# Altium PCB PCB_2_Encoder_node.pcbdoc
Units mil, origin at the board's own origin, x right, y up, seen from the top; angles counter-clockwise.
Board outline 2066.54 x 1941.84 mil, 2 copper layers (Top Layer, Bottom Layer), stack 2.757 mil thick; 20 components, 22 nets, 103 pads, 62 vias.
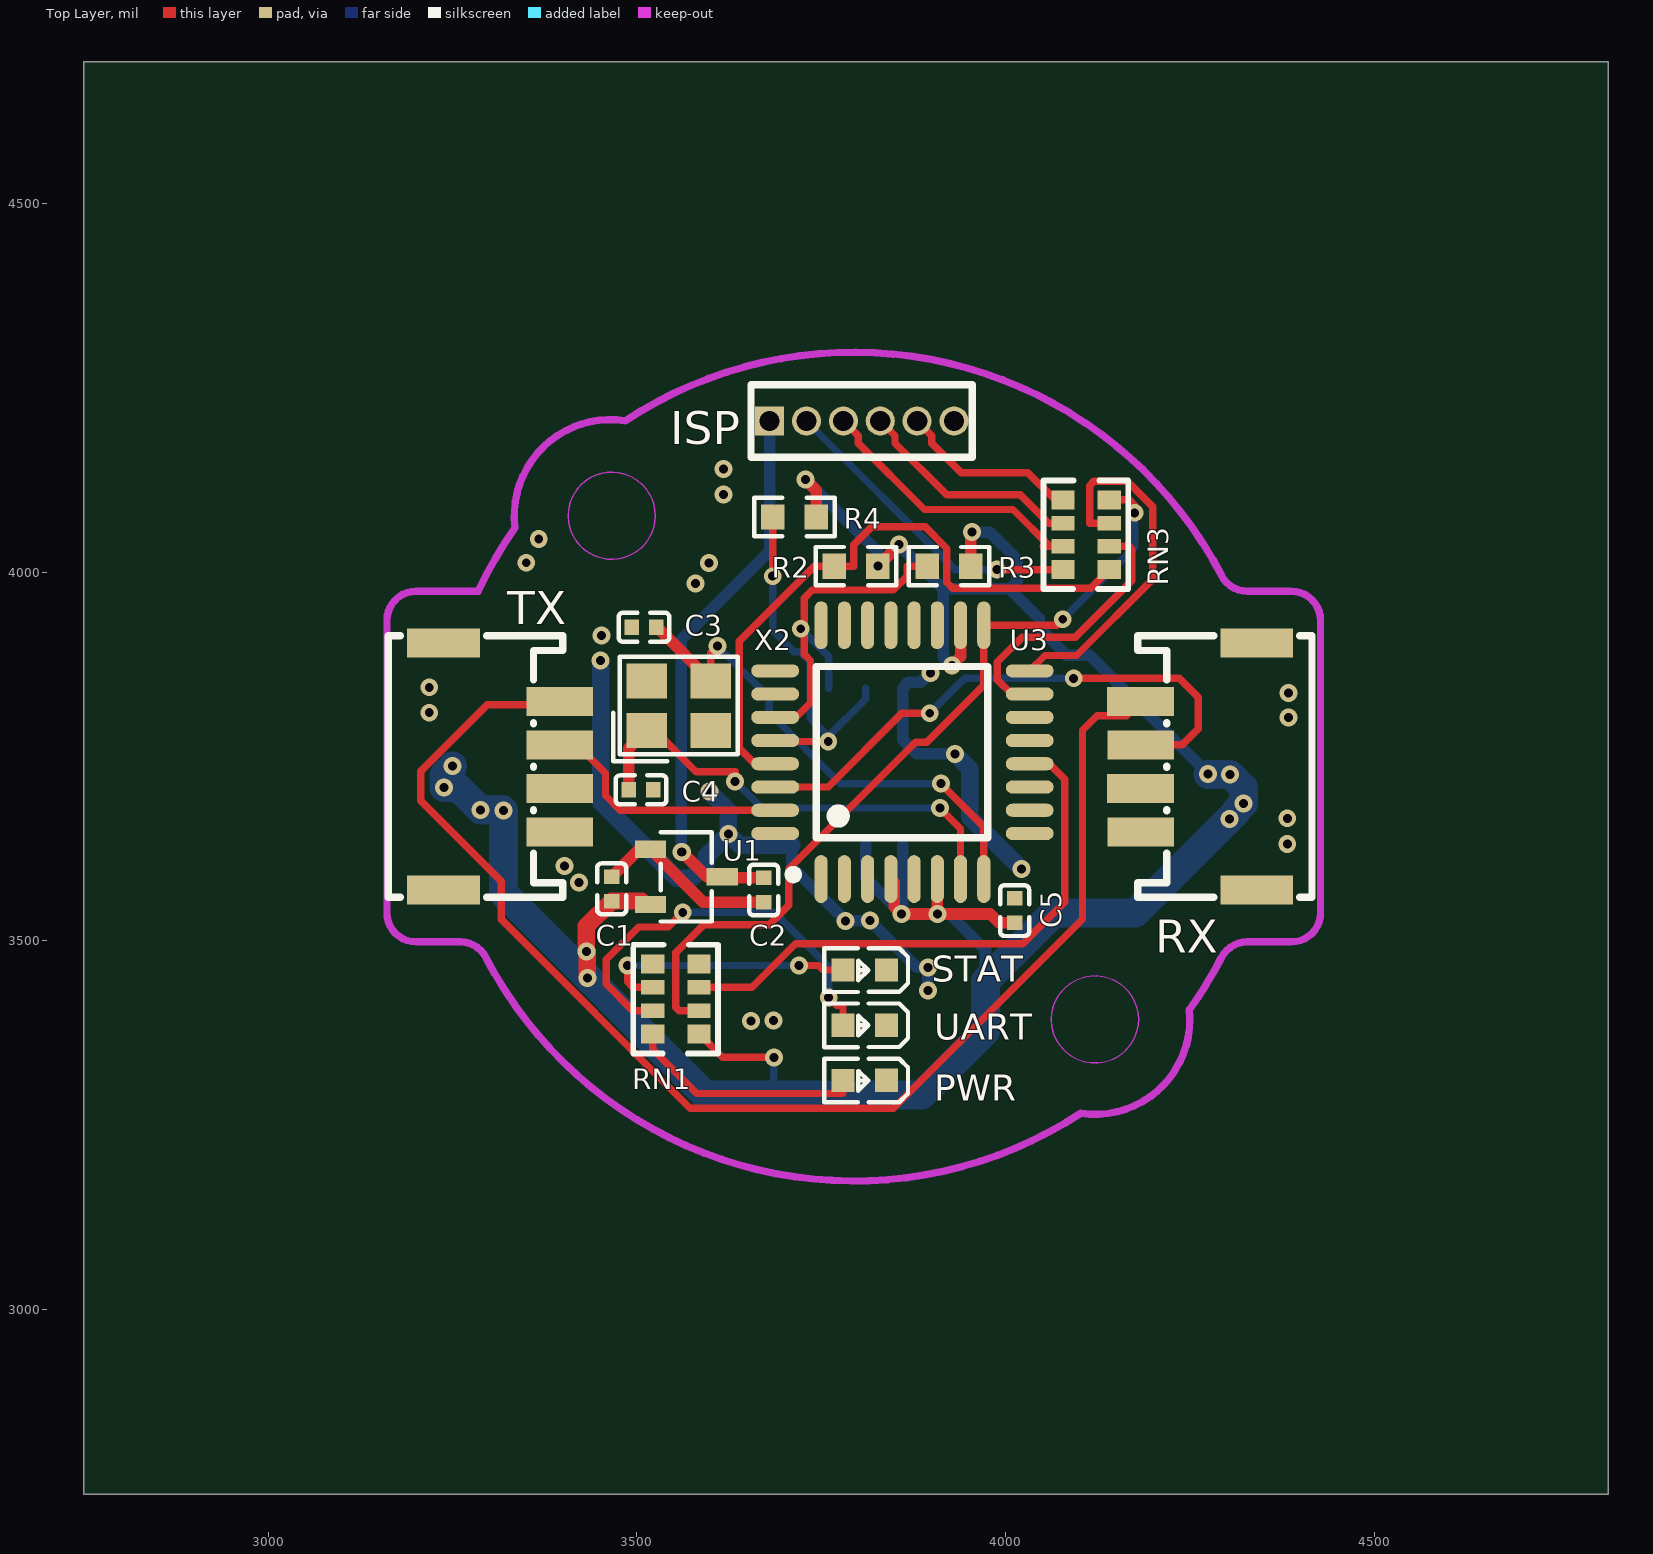
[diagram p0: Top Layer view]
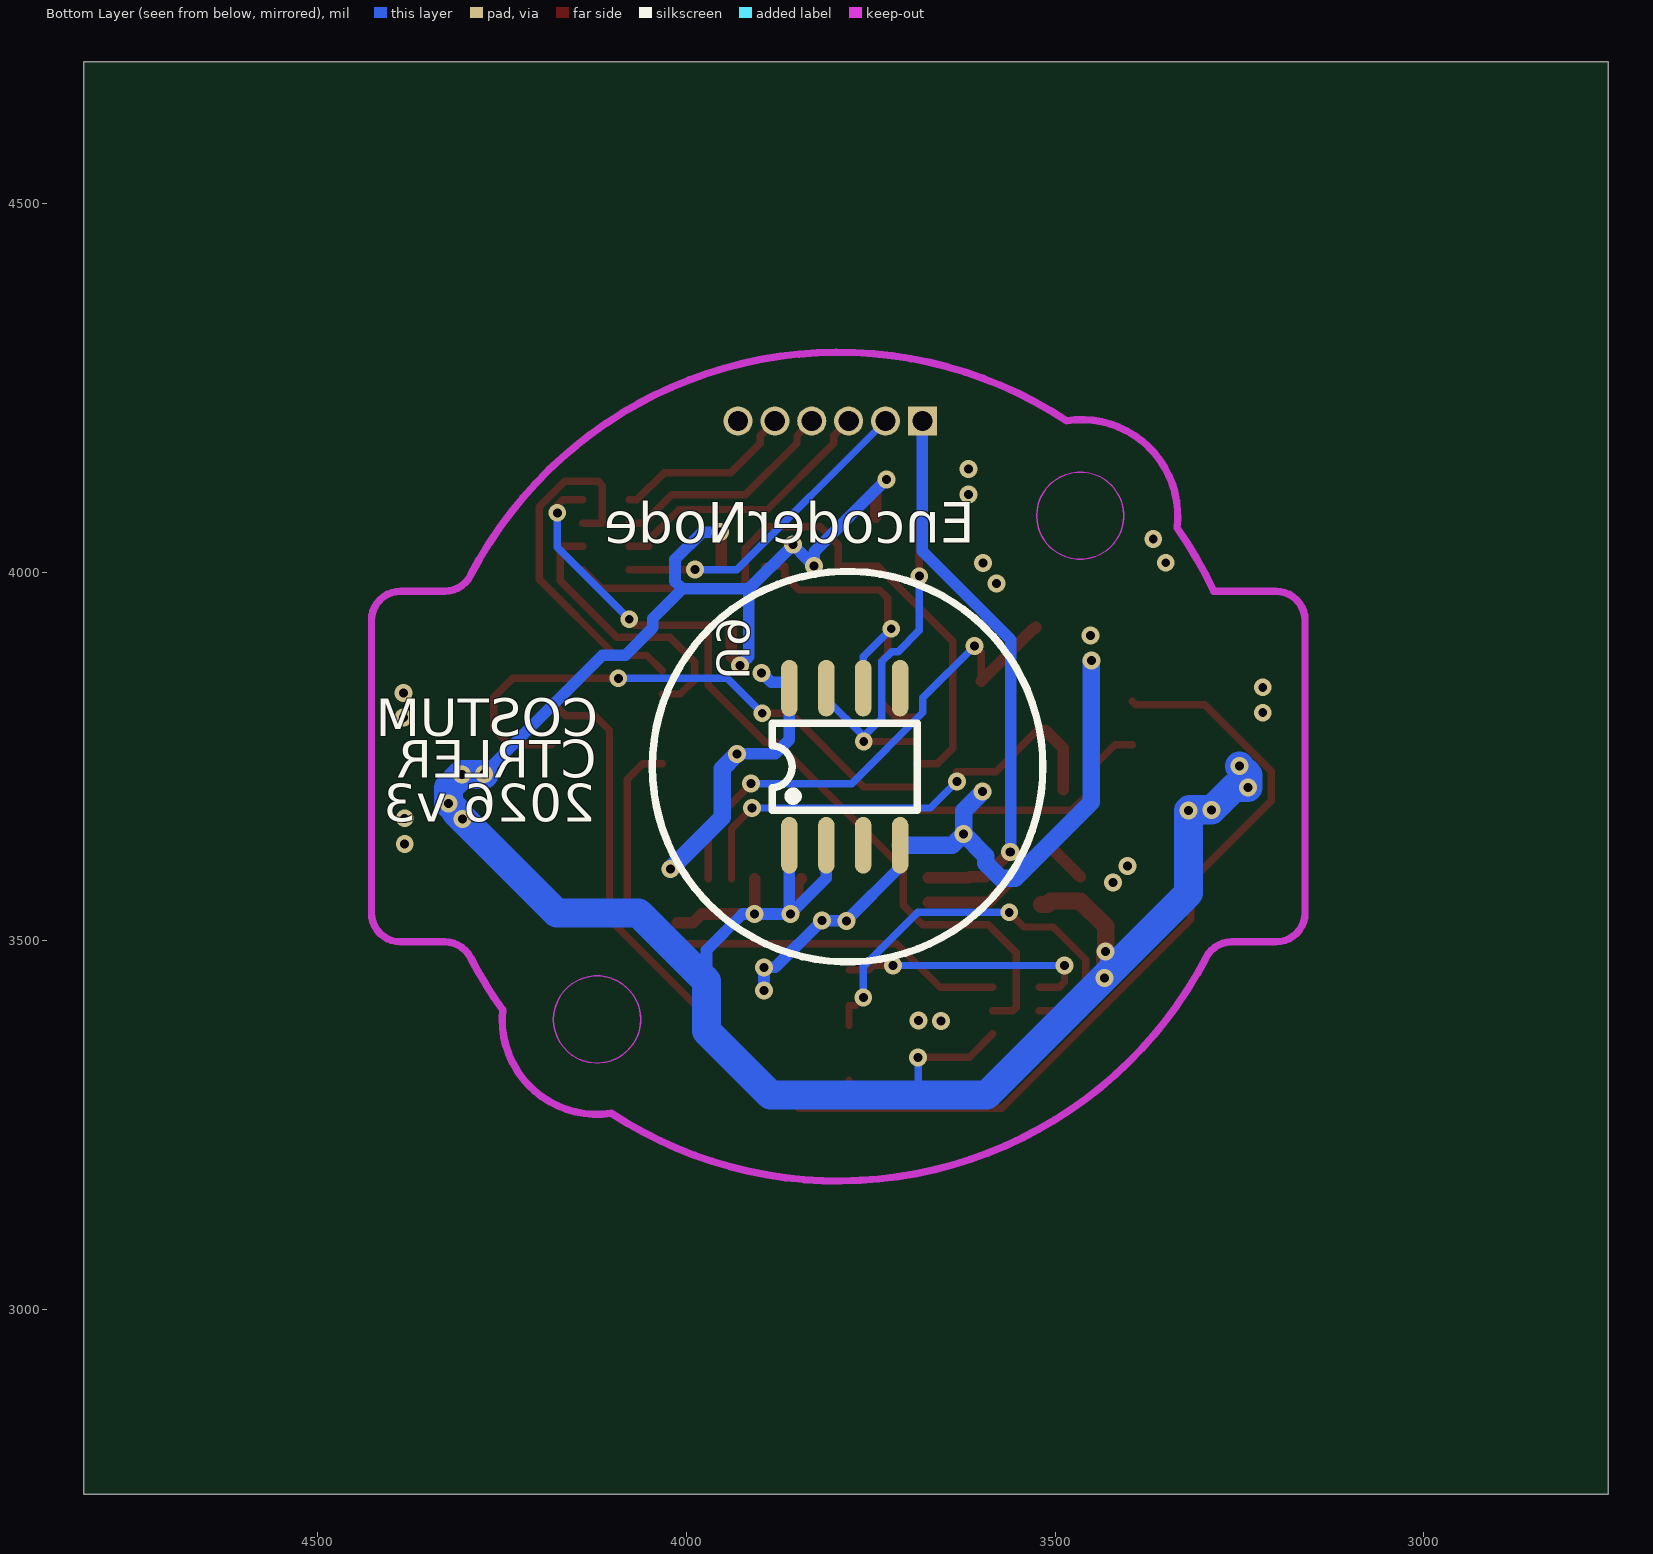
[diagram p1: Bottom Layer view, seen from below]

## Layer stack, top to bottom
Top Solder Mask Layer: solder mask 0.394, Dk 3.3
Top Layer: signal copper 1.379
Bottom Layer: signal copper 1.378
Bottom Solder Mask Layer: solder mask 0.394, Dk 3.3

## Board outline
4816.54,2750 2750,2750 2750,4691.84 4816.54,4691.84

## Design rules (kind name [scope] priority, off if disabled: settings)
BoardOutlineClearance Default [All] p0: genericclearance=10 ignorepadtopadclearanceinfootprint=FALSE except(0: Arc-SplitContinuation Track-SplitContinuation SMDPad-SplitContinuation THPad-SplitContinuation Via-SplitContinuation Fill-SplitContinuation Poly-SplitContinuation Region-SplitContinuation Text-SplitContinuation)
BoardOutlineClearance otherClearance [All] p0: genericclearance=10 ignorepadtopadclearanceinfootprint=FALSE except(0: Arc-SplitContinuation Track-SplitContinuation SMDPad-SplitContinuation THPad-SplitContinuation Via-SplitContinuation Fill-SplitContinuation Poly-SplitContinuation Region-SplitContinuation Text-SplitContinuation)
Clearance Default [All] p1: gap=7 ignorepadtopadclearanceinfootprint=FALSE
Clearance otherClearance [All] p1: gap=7 ignorepadtopadclearanceinfootprint=FALSE
DiffPairsRouting differentialPair [All] p1: maxuncoupledlength=10 minlimit=5 maxlimit=Infinity mostfreqgap=6 toplayer_minwidth=5 toplayer_prefwidth=100 toplayer_maxwidth=100 bottomlayer_minwidth=5 bottomlayer_prefwidth=100 bottomlayer_maxwidth=100
PasteMaskExpansion pasteMaskExpansion [All] p1: expansion=0
PlaneConnect innerPlane [All] p1: planeconnectstyle=Relief reliefexpansion=20 reliefentries=4 reliefconductorwidth=10 reliefairgap=10
PolygonConnect copperRegion [All] p1: connectstyle=Relief reliefentries=4 reliefconductorwidth=10 polygonreliefangle="90 Angle" airgapwidth=10
RoutingVias Default [All] p1: viastyle="Through Hole" holewidth=12.008000000000001 minholewidth=12.008000000000001 maxholewidth=1181 width=12.008000000000001 minwidth=12.008000000000001 maxwidth=1181
SolderMaskExpansion Common [IsVia] p1: useseparateexpansions=TRUE expansion=-1000 expansionbottom=-1000
SolderMaskExpansion Common [All] p2: useseparateexpansions=TRUE expansion=2 expansionbottom=2
Width Default [All] p1: maxlimit=1000 minlimit=10 preferedwidth=10

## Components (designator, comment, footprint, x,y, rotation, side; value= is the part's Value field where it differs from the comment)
C1 "1uF" C0402 3465.71,3570.71 r270 top
C2 "1uF" C0402 3671.77,3569.13 r90 top
C3 "15pf" C0402 3509.41,3925.27 r0 top
C4 "15pf" C0402 3505.47,3704.8 r0 top
C5 "100pf" C0402 4011.79,3541.16 r90 top
ISP "6PIN" HDR-TH_6P-P1.27-V-M 3804.68,4204.8 r0 top
PWR "GL0603UG01" LED0603-RD 3808.62,3311.1 r180 top
R2 "10kΩ" R0603 3796.81,4007.95 r0 top
R3 "10kΩ" R0603 3922.79,4007.95 r0 top
R4 "10kΩ" R0603 3713.53,4074.64 r0 top
RN1 "4.7kΩ" RES-ARRAY-SMD_0603-8P-L3.2-W1.6-BL 3552.72,3421.33 r90 top
RN3 "1kΩ" RES-ARRAY-SMD_0603-8P-L3.2-W1.6-BL 4108.72,4050.6 r90 top
RX "RX" CONN-SMD_4P-P1.50_ZX-ZH1.5-4PWT 4261.38,3736.29 r90 top
STAT "GL0603UG01" LED0603-RD 3808.59,3460.73 r180 top
TX "TX" CONN-SMD_4P-P1.50_ZX-ZH1.5-4PWT 3316.49,3736.29 r270 top
U1 "XC6206P332MR" SOT-23-3_L2.9-W1.6-P1.90-LS2.8-BR 3566.97,3586.86 r180 top
U3 "ATMEGA328P-AU" TQFP-32_L7.0-W7.0-P0.80-LS9.0-BL 3859.77,3755.96 r0 top
U9 "AS5600-ASOT" SOIC-8_L5.0-W4.0-P1.27-LS6.0-BL 3784.97,3736.26 r180 bottom
UART "GL0603UG01" LED0603-RD 3808.59,3385.93 r180 top
X2 "8MHz" CRYSTAL-SMD_4P-L3.2-W2.5-BL 3556.65,3818.97 r0 top

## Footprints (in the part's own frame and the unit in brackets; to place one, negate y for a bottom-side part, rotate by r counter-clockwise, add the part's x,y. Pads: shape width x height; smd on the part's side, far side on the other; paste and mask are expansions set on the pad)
C0402 [mm]
  rect 0.5x0.54 smd paste+0 mask+0.051: 1(-0.42,0) 2(0.42,0)
  silkscreen extent -0.87,-0.5 0.87,0.5
CONN-SMD_4P-P1.50_ZX-ZH1.5-4PWT [mm]
  rect 1x2.3 smd paste+0 mask+0.05: 1(-2.25,2) 2(-0.75,2) 3(0.75,2) 4(2.25,2)
  rect 1x2.5 smd paste+0 mask+0.05: 5(4.25,-2) 6(-4.25,-2)
  silkscreen extent -4.5,-3.9 4.5,2.1
CRYSTAL-SMD_4P-L3.2-W2.5-BL [mm]
  rect 1.4x1.2 smd paste+0 mask+0.051: 1(-1.1,-0.85) 2(1.1,-0.85) 3(1.1,0.85) 4(-1.1,0.85)
  silkscreen extent -2.26,-1.91 2.03,1.68
HDR-TH_6P-P1.27-V-M [mm]
  rect 1x1 hole 0.7 paste+0 mask+0.051: 1(-3.175,0)
  round 1 hole 0.7 paste+0 mask+0.051: 2(-1.905,0) 3(-0.635,0) 4(0.635,0) 5(1.905,0) 6(3.175,0)
  silkscreen extent -3.82,-1.25 3.8,1.25
LED0603-RD [mm]
  rect 0.8x0.8 smd paste+0 mask+0.051: 1(-0.749,0) 2(0.749,0)
  silkscreen extent -1.49,-0.75 1.39,0.76
R0603 [mil]
  rect 31.75x34.02 smd paste-3937.01 mask+2: 1(-29.66,0) 2(29.65,0)
  silkscreen extent -55,-26 55,26
RES-ARRAY-SMD_0603-8P-L3.2-W1.6-BL [mm]
  rect 0.65x0.8 smd paste+0 mask+0.051: 1(-1.2,-0.8) 4(1.2,-0.8) 5(1.2,0.8) 8(-1.2,0.8)
  rect 0.5x0.8 smd paste+0 mask+0.051: 2(-0.4,-0.8) 3(0.4,-0.8) 6(0.4,0.8) 7(-0.4,0.8)
  silkscreen extent -1.87,-1.45 1.87,1.47
SOIC-8_L5.0-W4.0-P1.27-LS6.0-BL [mil]
  oval 22.38x76.78 smd paste+0 mask+2: 1(-75,-106.5) 2(-25,-106.5) 3(25,-106.5) 4(75,-106.5) 5(75,106.5) 6(25,106.5) 7(-25,106.5) 8(-75,106.5)
  silkscreen extent -98,-59 98,59
SOT-23-3_L2.9-W1.6-P1.90-LS2.8-BR [mm]
  rect 1.07x0.6 smd paste+0 mask+0.051: 1(1.235,-0.95) 2(1.235,0.95) 3(-1.235,0)
  silkscreen extent -0.88,-1.54 0.88,1.54
TQFP-32_L7.0-W7.0-P0.80-LS9.0-BL [mm]
  oval 0.45x1.65 smd paste+0 mask+0.051: 1(-2.8,-4.369) 2(-2,-4.369) 3(-1.2,-4.369) 4(-0.4,-4.369) 5(0.4,-4.369) 6(1.2,-4.369) 7(2,-4.369) 8(2.8,-4.369) 17(2.8,4.369) 18(2,4.369) 19(1.2,4.369) 20(0.4,4.369) 21(-0.4,4.369) 22(-1.2,4.369) 23(-2,4.369) 24(-2.8,4.369)
  oval 1.65x0.45 smd paste+0 mask+0.051: 9(4.381,-2.8) 10(4.381,-2) 11(4.381,-1.2) 12(4.381,-0.4) 13(4.381,0.4) 14(4.381,1.2) 15(4.381,2) 16(4.381,2.8) 25(-4.381,2.8) 26(-4.381,2) 27(-4.381,1.2) 28(-4.381,0.4) 29(-4.381,-0.4) 30(-4.381,-1.2) 31(-4.381,-2) 32(-4.381,-2.8)
  silkscreen extent -3.91,-4.36 2.94,2.95

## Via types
v1: diameter 24.41, hole 12.2, Top Layer to Bottom Layer, 44 vias
v2: diameter 24.02, hole 12.01, Top Layer to Bottom Layer, 18 vias

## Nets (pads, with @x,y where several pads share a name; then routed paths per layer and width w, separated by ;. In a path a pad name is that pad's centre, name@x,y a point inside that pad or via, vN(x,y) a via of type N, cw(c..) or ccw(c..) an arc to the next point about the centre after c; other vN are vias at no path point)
3V3: C1.2 C5.1 R2.2 R3.2 R4.2 RN1.1 RX.2 TX.3 U1.2 U3.4 U3.6 U3.18 U9.1 U9.2 | length 3855.3
  Top Layer w10: RN1.1 3616.12,3342.19 v1(3685.56,3342.19)
  Top Layer w15.75: v1(3728.51,4125.46) 3743.19,4110.78 R4.2 ; R2.2@3826.47,4007.96 3834.97,4016.46 v1(3854.98,4037.21) ; U3.4 3848.78,3579.25 3848.78,3546.53 v1(3858.78,3536.53) 3978.78,3536.53 3990.69,3524.62 C5.1 ; v1(3907.04,3536.53) U3.6 ; v1(3926.69,3873.7) 3938.54,3885.55 U3.18 ; R3.2 3952.45,4052.33 v1(3954.27,4054.15)
  Top Layer w23.62: v1(3432.61,3449.75) 3432.61,3485.61 v1(3431.43,3485.61) 3431.43,3519.89 C1.2 3505.71,3554.17 3510.41,3549.46 U1.2
  Bottom Layer w10: v1(3685.56,3342.19) 3685.56,3302.19 3687.62,3300.13 3687.62,3291.36
  Bottom Layer w15.75: v1(3431.43,3485.61) 3431.43,3449.75 v1(3432.61,3449.75) 3437.68,3449.75 3440.46,3446.97 v1@3440.46,3443.48 ; v1(3728.51,4125.46) 3826.46,4027.51 v1(3826.46,4007.95) 3834.97,4016.46 v1(3854.98,4037.21) ; U9.2 3810,3585.31 v1(3858.78,3536.53) ; v1(3854.98,4037.21) 3914.98,3977.2 ; U9.1 3860,3537.75 v1(3858.78,3536.53) ; v1(3926.69,3873.7) 3914.98,3885.4 3914.98,3977.2 ; v1(3954.27,4054.15) 3978.04,4054.15 4014.98,4017.2 4014.98,3987.2 4004.98,3977.2 3914.98,3977.2 ; 3972.37,3445.86 3972.37,3487.56 3923.47,3536.56 3907.07,3536.56 v1(3858.78,3536.53) ; 4004.97,3977.16 4044.97,3937.16 4044.97,3924.46 4082.17,3887.16 4113.37,3887.16 v1@4274.17,3726.36
  Bottom Layer w39.37: v1(3250.19,3736.98) 3238.37,3725.16 v1(3238.37,3707.82) 3257.68,3707.82 v1(3287.62,3677.88) 3317.96,3677.88 v1(3319.14,3676.7) 3319.14,3564.8 3592.57,3291.36 3885.71,3291.36 3972.39,3378.04 3972.39,3445.81 4064.59,3538.01 4175.3,3538.01 v1(4302.96,3665.67) 4311.87,3674.57 4311.87,3676.55 v1(4321.87,3686.55) 4321.87,3707.82 4303.75,3725.95 v1@4274.17,3725.96
  other v1: 4274.2,3726.34 4303.75,3725.95
GND: C1.1 C2.1 C3.1 C4.2 C5.2 ISP.6 PWR.1 RX.1 STAT.1 TX.4 U1.1 U3.3 U3.5 U3.21 U9.4 U9.8 UART.1 X2.2 X2.4 | length 1542.5
  Top Layer w15.75: C1.1 3505.71,3627.25 3508.69,3624.26 U1.1 3590.01,3552.59 C2.1
  Bottom Layer w15.75: U9.4 3710,3600.25 v1(3782.88,3527.37) ; v1(3782.88,3527.37) v1(3815.58,3527.77) ; v1(3815.58,3527.77) 3879.01,3464.33 v1(3894.38,3464.33) v1(3894.38,3432.81) ; U9.8 3859.97,3772.76 3879.27,3753.56 v1@3931.07,3753.56 ; U9.8 3867.74,3850.54 3884.63,3850.54 v1(3897.53,3863.45)
  Bottom Layer w23.62: v1@3450.77,3879.96 3450.77,3688.16 3553.67,3585.16 3573.67,3585.16 3593.67,3605.16 3593.67,3615.16 v1(3623.7,3645.18) ; v1(3598.09,3702.31) 3623.7,3676.7 v1(3623.7,3645.18) 3639.08,3629.8 U9.4 ; v1(3931.02,3753.53) 3951.25,3733.3 3951.25,3667.5 v1(4021.25,3597.5)
  other v1: 3654.43,3391.44 3685.17,3392.23 3421.19,3578.98 3401.88,3601.44 4383.33,3802.78 4382.94,3835.87 3450.74,3880 3451.92,3913.88 3579.18,3984.8 3597.7,4012.38 3617.4,4105.37 3617,4140.04
  other v2: 4381.46,3631.43 4381.46,3666.22 3218.47,3809.45 3218.47,3843.78 3349.96,4012.67 3366.89,4044.96
ISP_2: ISP.2 RN3.8 | length 431
  Top Layer w10: v2@3988.05,4003.36 RN3.8
  Bottom Layer w10: ISP.2 3931.12,4003.36 v2@3988.05,4003.36
  other v2: 3988.05,4003.36
ISP_3: ISP.3 RN3.7 | length 400.5
  Top Layer w10: ISP.3 3799.68,4184.8 3799.68,4174.8 3889.68,4084.8 4009.68,4084.8 4059.63,4034.85 RN3.7 4050.48,4034.85
ISP_4: ISP.4 RN3.6 | length 310.7
  Top Layer w10: ISP.4 3849.68,4184.8 3849.68,4174.8 3919.68,4104.8 4019.68,4104.8 4058.13,4066.35 RN3.6
ISP_5: ISP.5 RN3.5 | length 247.7
  Top Layer w10: ISP.5 3899.68,4184.8 3899.68,4174.8 3939.68,4134.8 4029.68,4134.8 4066.64,4097.84 RN3.5
LED_STAT: RN1.3 U3.12 | length 766.2
  Top Layer w10: RN1.3 3655.85,3437.09 3714.85,3496.09 4023.05,3496.09 4079.85,3552.89 4079.85,3719.31 4058.93,3740.23 U3.12
MISO: RN3.3 U3.16 | length 495.9
  Top Layer w10: U3.16 4053.05,3886.97 4095.67,3886.97 4198.84,3990.14 4198.84,4088.66 4164.63,4122.87 4119.09,4122.87 4113.4,4117.18 4113.4,4066.42 ; 4113.47,4066.35 RN3.3@4140.21,4066.35
MOSI: RN3.2 U3.15 | length 378.7
  Top Layer w10: U3.15 4007.88,3834.72 3988.35,3854.25 3988.35,3878.13 4022.14,3911.92 4094.15,3911.92 4170.73,3988.5 4170.73,4031.07 4166.95,4034.85 RN3.2@4140.21,4034.85
PASS: RX.4 TX.1 | length 1824.9
  Top Layer w10: TX.1 3390.45,3820.09 3296.85,3820.09 3206.85,3730.09 3206.85,3690.09 3315.79,3581.15 3315.79,3529.36 3571.9,3273.25 3847.72,3273.25 4103.83,3529.36 4103.83,3785.47 4123.53,3805.18 4162.93,3805.18 RX.4
PWR_2: PWR.2 RN1.8 | length 321.4
  Top Layer w10: RN1.8@3521.27,3374.06 3521.27,3352.86 3580.77,3293.36 3779.17,3293.36 PWR.2@3779.17,3311.06
RST: R2.1 RN3.1 U3.29 | length 857.3
  Top Layer w10: U3.29 3659.44,3740.23 3638.58,3761.09 3638.58,3906.46 3740.07,4007.95 R2.1 3794.02,4007.95 ; 3793.97,4007.96 3793.97,4036.86 3818.37,4061.26 3890.47,4061.26 3920.07,4031.66 3920.07,3985.86 3927.97,3977.96 4114.77,3977.96 RN3.1
RX: RX.3 U3.30 | length 774.9
  Top Layer w10: U3.30 3758.97,3708.74 3858.92,3808.69 v2(3896.74,3808.69) ; v2(4091.77,3855.97) 4235.17,3855.96 4260.77,3830.36 4260.77,3787.76 4238.87,3765.86 ; RX.3 4238.9,3765.82
  Bottom Layer w10: v2(3896.74,3808.69) 3944.02,3855.97 v2(4091.77,3855.97)
SCK: RN1.2 RN3.4 U3.17 | length 1127.2
  Top Layer w10: RN1.2 3557.47,3405.59 3552.72,3410.34 3552.72,3483.93 3590.64,3521.85 3679.27,3521.85 3705.89,3548.47 3705.89,3597.61 3877.54,3769.26 3892.84,3769.26 3970.04,3846.46 U3.17 4068.93,3927.98 v2(4077.06,3936.11) ; RN3.4 4166.95,4097.84 4174.52,4090.27 v2(4174.52,4080.25)
  Bottom Layer w10: v2(4077.06,3936.11) 4174.52,4033.57 v2(4174.52,4080.25)
SCL: R4.1 U3.28 U9.7 | length 499.7
  Top Layer w10: v2(3683.88,3994.52) R4.1 ; U3.28 3688.62,3770.41 v2(3759.28,3770.41)
  Bottom Layer w10: v2(3683.88,3994.52) 3683.88,3921.02 3712.65,3892.25 3721.51,3892.25 3735,3878.76 3735,3801.59 v2@3759.28,3777.31 ; v2(3759.28,3770.41) v2@3759.28,3777.31 ; U9.7 3810,3828.03 v2@3759.28,3777.31
SDA: R3.1 U3.27 U9.6 | length 494.4
  Top Layer w10: U3.27 3715.52,3803.22 3735.13,3822.83 3735.13,3880.2 3726.49,3888.84 v2@3726.49,3923.13 ; v2(3721.92,3923.13) v2@3726.49,3923.13 ; R3.1 3866.27,4007.95 3866.27,3994.52 3847.45,3975.7 3737.6,3975.7 3726.49,3964.59 v2@3726.49,3923.13
  Bottom Layer w10: v2(3721.92,3923.13) 3760,3885.05 U9.6
STAT_2: RN1.6 STAT.2 | length 353.9
  Top Layer w10: v2(3487.19,3466.76) 3487.19,3444.38 3494.48,3437.09 RN1.6 ; v2(3719.46,3466.76) 3746.33,3466.76 3752.39,3460.7 STAT.2
  Bottom Layer w10: v2(3487.19,3466.76) v2(3719.46,3466.76)
TOSC1: C4.1 U3.7 X2.1 | length 647.4
  Top Layer w10: X2.1@3513.37,3785.56 3523.97,3785.56 3579.97,3729.46 3633.17,3729.46 v1(3633.16,3716.1) ; v1(3910.53,3680.24) 3938.54,3652.24 U3.7
  Top Layer w15.75: C4.1 3488.94,3761.1 X2.1@3513.35,3785.51
  Bottom Layer w10: v1(3633.16,3716.1) 3669.02,3680.24 v1(3910.53,3680.24)
TOSC2: C3.2 U3.8 X2.3 | length 700.3
  Top Layer w10: X2.3 3599.96,3890.53 v1(3609.12,3899.7) ; v1(3911.72,3713.34) 3970.04,3655.02 U3.8
  Top Layer w15.75: C3.2 3528.77,3922.44 3529.96,3922.44 X2.3
  Bottom Layer w10: v1(3609.12,3899.7) 3679.12,3829.7 3679.12,3809.7 3775.49,3713.34 v1(3911.72,3713.34)
TX: TX.2 U3.31 | length 346.3
  Top Layer w10: TX.2 3418.67,3765.82 3457.27,3727.22 3457.27,3697.22 3477.27,3677.22 U3.31
UART_2: RN1.7 UART.2 | length 561.8
  Top Layer w10: RN1.7 3494.48,3405.59 3458.37,3441.7 3458.37,3474.92 3502.37,3518.92 3542.21,3518.92 v2(3562.08,3538.79) ; v2(3759.77,3423.3) 3770.43,3412.64 3779.13,3412.64 UART.2
  Bottom Layer w10: v2(3562.08,3538.79) 3686.22,3538.79 3759.77,3465.24 v2(3759.77,3423.3)
VCC: C2.2 ISP.1 U1.3 | length 759.6
  Top Layer w15.75: v1(3560.66,3620.75) 3594.54,3586.86 U1.3 3616.78,3585.67 C2.2
  Bottom Layer w15.75: v1(3560.66,3620.75) 3559.87,3621.53 3559.87,3908.37 3631.94,3980.43 3679.68,4028.17 ISP.1
pads on no net: RN1.4 RN1.5 RX.5 RX.6 TX.5 TX.6 U3.1 U3.2 U3.9 U3.10 U3.11 U3.13 U3.14 U3.19 U3.20 U3.22 U3.23 U3.24 U3.25 U3.26 U3.32 U9.3 U9.5

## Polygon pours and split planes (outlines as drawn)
3V3 on Top Layer (solid, remove dead copper, pour order 4): 4103.9,3685.11 4143.27,3645.74 4261.38,3645.74 4320.43,3645.74 4340.11,3665.43 4340.11,3724.48 4320.43,3744.17 4123.58,3744.17 4103.9,3724.48
3V3 on Top Layer (solid, remove dead copper, pour order 8): 3218.76,3697.58 3258.13,3658.21 3376.24,3658.21 3435.29,3658.21 3454.98,3677.9 3454.98,3736.95 3435.29,3756.64 3238.44,3756.64 3218.76,3736.95
3V3 on Bottom Layer (solid, remove dead copper, pour order 18): 3401.09,3499.39 3419.61,3508.85 3458.62,3508.46 3469.65,3497.03 3471.22,3429.66 3443.25,3426.51 3425.13,3433.6 3406.21,3472.21 3406.21,3472.6
GND on Bottom Layer (solid, remove dead copper, pour order 20): 3000,4040.95 3399.91,4440.86 4074.04,4440.86 4566.54,3948.36 4566.54,3729.69 4529.51,3692.65 4529.51,3089.04 4440.46,3000 3166.66,3000 3166.66,3003.94
GND on Top Layer (solid, remove dead copper, pour order 10): 3067.37,4094.34 3414.88,4441.84 3540.96,4441.84 3548.84,4433.96 4206.82,4433.96 4564.57,4076.21 4564.57,3944.22 4509.41,3889.06 4509.41,3075.84 4506.66,3073.09 3128.05,3073.09 3128.05,3078.6

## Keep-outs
Board Outline Layer:
  region: 4179.73,3393.66 cw(c4120.67,3393.66) 4061.61,3393.66 cw(c4120.67,3393.66)
  circle w0.1: c4120.67,3393.66 r59.05
  region: 4179.73,3393.66 cw(c4120.67,3393.66) 4061.61,3393.66 cw(c4120.67,3393.66)
  region: 3524.86,4076.45 cw(c3465.81,4076.45) 3406.76,4076.45 cw(c3465.81,4076.45)
  circle w0.1: c3465.81,4076.45 r59.05
  region: 3524.86,4076.45 cw(c3465.81,4076.45) 3406.76,4076.45 cw(c3465.81,4076.45)
  lines w10: 3161.15,3538.14 3161.15,3934.64 cw(c3200.52,3934.64) 3200.52,3974.01 3284.86,3974.01 cw(c3793.77,3736.39) 3334.73,4060.02 cw(c3464.16,4076.25) 3484.34,4205.12 cw(c3793.77,3736.39) 4292.23,3995.24 ccw(c4327.17,4013.38) 4327.17,3974.01 4387.03,3974.01 cw(c4387.03,3934.64) 4426.4,3934.64 4426.4,3538.14 cw(c4387.03,3538.14) 4387.03,3498.77 4327.17,3498.77 ccw(c4327.17,3459.4) 4292.23,3477.54 cw(c3793.77,3736.39) 4248.65,3406.93 cw(c4120.67,3393.66) 4101.36,3266.45 cw(c3793.77,3736.39) 3295.32,3477.54 ccw(c3260.38,3459.4) 3260.38,3498.77 3200.52,3498.77 cw(c3200.52,3538.14) 3161.15,3538.14

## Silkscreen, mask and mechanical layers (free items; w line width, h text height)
Bottom Silkscreen Layer:
  circle w10: c3781.06,3736.3 r264.69
  text "EncoderNode" at 3608.23,4039.44 h55.12
  text "COSTUM" at 4118.86,3777.24 h51.18
  text "CTRLER" at 4120.83,3721.33 h51.18
  text "2026 v3" at 4122.8,3661.49 h51.18
Mechanical Layer:
  circle w0.1: c4120.67,3393.66 r59.05
  circle w0.1: c3465.81,4076.45 r59.05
